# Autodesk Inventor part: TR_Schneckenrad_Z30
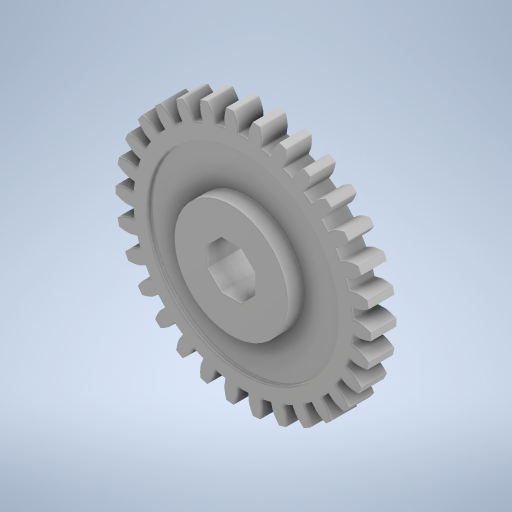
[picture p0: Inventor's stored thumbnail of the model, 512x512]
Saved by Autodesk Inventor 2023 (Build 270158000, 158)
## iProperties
Created: 2023-11
Part Number: TR_Schneckenrad_Z30
Material: PC/ABS-Kunststoff
Document SubType Name: Modeling
Designer: AdminForWorker
Density: 0.357273 g/cm^3
Appearance: Glatt - Marine
Title: Component1
Author: AdminForWorker
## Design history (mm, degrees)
feature "Body1"
sketch "Skizze2"
  geometry: C1 r 12 at (-13.754, 6.632); 1 further point
  constraints: 1 centre point, 1 coincident
  dimensions: "d0" = 24 diameter of C1
extrude "Extrusion1" cut sketch "Skizze2" distance "d1" = 0.5; taper "d2" = 0 deg
workplane "Arbeitsebene2"
mirror "Spiegeln1"
sketch "Skizze4"
  geometry: C1 r 12 at (-13.754, 6.632) reference; C2 r 12 at (-13.754, 6.632) reference; C3 r 7.1 at (-13.754, 6.632); 1 further point
  constraints: 1 centre point, 1 coincident
  dimensions: "d6" = 14.2 diameter of C3
extrude "Extrusion3" join sketch "Skizze4" stored distance "d7" = 6.2; taper "d8" = 0 deg
sketch "Skizze5"
  geometry: L1 (3, -1.243)-(1.243, -3); L2 (1.243, -3)-(-1.243, -3); L3 (-1.243, -3)-(-3, -1.243); L4 (-3, -1.243)-(-3, 1.243); L5 (-3, 1.243)-(-1.243, 3); L6 (-1.243, 3)-(1.243, 3); L7 (1.243, 3)-(3, 1.243); L8 (3, 1.243)-(3, -1.243); C1 r 7.1 at (0, 0) reference; 2 further points
  constraints: 16 end point, 1 coincident, 1 horizontal, 17 other
  dimensions: "d9" = 6 distance between parallel lines of L8 L4 (= AchteckUmkreis)
extrude "Extrusion4" cut sketch "Skizze5" extent not by distance; stored distance "d10" = 0; taper "d11" = 0 deg
body "Solid1"
other parameters: "Radius" = 2.075 [user parameter], "Fasen" = 0.5 [user parameter], "Dicke" = 0.8 [user parameter], "Breitloch" = 2 [user parameter], "Langloch" = 32 [user parameter], "AchteckUmkreis" = 6 [user parameter; used in 1 equation term], "DAchsAufnahme" = 4.1 [user parameter], "AchsDurchmesser" = 4 [user parameter], "AchsFase" = 0.5 [user parameter]
